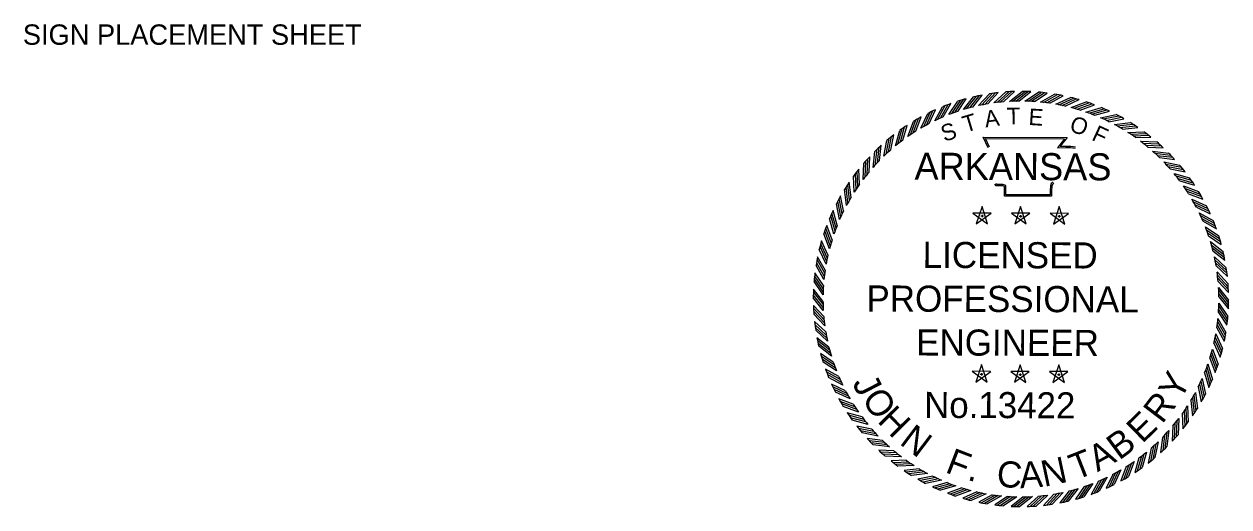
# Model space of a CAD drawing. Extents: x 620861 to 621178, y 415479 to 415559.
# Drawn here: x 621155.59 to 621178.3, y 415532.61 to 415541.71 of the extents above; entities that cross this region are included whole.
import ezdxf

# ---------------------------------------------------------------- set-up
doc = ezdxf.new("R2010")
doc.units = 0
doc.layers.add('Default', color=7, linetype='Continuous')
doc.layers.add('R_Border', color=7, linetype='Continuous')

# ---------------------------------------------------------------- blocks, each defined once
blk = doc.blocks.new('STAR')
at = {"layer": 'Default'}
for p, q in [((0.0587, 0.0188), (-0.059, 0.0189)), ((-0.0589, 0.0188), (0.0363, -0.0505)), ((-0.0001, 0.0615), (-0.0366, -0.0504)), ((-0.0365, -0.0503), (0.0589, 0.0188)), ((-0.0085, 0), (0.009, 0)), ((0.0362, -0.0503), (0, 0.0617)), ((0, 0.0063), (0, -0.0085))]:
    blk.add_line(p, q, dxfattribs=at)
blk = doc.blocks.new('RP')
at = {"layer": 'Default'}
for p, q in [((-0.0781, 1.2656), (0.003, 1.33)), ((-0.058, 1.2667), (0.0216, 1.3299)), ((-0.0375, 1.2674), (0.0405, 1.3294)), ((-0.0176, 1.2679), (0.059, 1.3287))]:
    blk.add_line(p, q, dxfattribs=at)
for radius, start, end in [(1.33, 87.45624, 89.86992), (1.268, 90.79335, 93.53072)]:
    blk.add_arc((0, 0), radius, start, end, dxfattribs=at)

msp = doc.modelspace()

# ---------------------------------------------------------------- linework, layer by layer
at = {"layer": 'Default'}
for points in [[(621173.763, 415539.378), (621173.672, 415539.577), (621175.255, 415539.572), (621175.122, 415539.407), (621175.23, 415539.408), (621175.32, 415539.409), (621175.409, 415539.399)], [(621173.786, 415539.389), (621173.711, 415539.552), (621175.203, 415539.548), (621175.07, 415539.381), (621175.23, 415539.383), (621175.318, 415539.384), (621175.407, 415539.374)], [(621175.003, 415538.711), (621174.976, 415538.689), (621174.967, 415538.656), (621174.957, 415538.574), (621174.957, 415538.465), (621174.073, 415538.468), (621174.074, 415538.615), (621174.074, 415538.648), (621174.038, 415538.659), (621173.912, 415538.66), (621173.89, 415538.694)], [(621174.987, 415538.73), (621174.954, 415538.703), (621174.942, 415538.661), (621174.932, 415538.576), (621174.932, 415538.49), (621174.098, 415538.493), (621174.099, 415538.615), (621174.099, 415538.667), (621174.042, 415538.684), (621173.926, 415538.685), (621173.911, 415538.708)]]:
    msp.add_lwpolyline(points, dxfattribs=at)

# ---------------------------------------------------------------- block references
for name, p, xscale, yscale, rotation in [('RP', (621174.382, 415536.528), 2.94327949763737, 2.9432794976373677, 13.30419999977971), ('RP', (621174.382, 415536.528), 2.9432794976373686, 2.9432794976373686, 8.804199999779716), ('RP', (621174.382, 415536.528), 2.9432794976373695, 2.9432794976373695, 4.304199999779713), ('RP', (621174.382, 415536.528), 2.9432794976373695, 2.943279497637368, -0.19580000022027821), ('RP', (621174.382, 415536.528), 2.9432794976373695, 2.943279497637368, -4.695800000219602), ('RP', (621174.382, 415536.528), 2.94327949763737, 2.9432794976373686, -9.195800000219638), ('RP', (621174.382, 415536.528), 2.94327949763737, 2.943279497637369, -13.695800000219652), ('RP', (621174.382, 415536.528), 2.9432794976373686, 2.9432794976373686, 22.304199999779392), ('RP', (621174.382, 415536.528), 2.943279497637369, 2.943279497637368, 17.80419999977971), ('RP', (621174.382, 415536.528), 2.94327949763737, 2.943279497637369, -18.19580000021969), ('RP', (621174.382, 415536.528), 2.9432794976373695, 2.943279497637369, -22.695800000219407), ('RP', (621174.382, 415536.528), 2.9432794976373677, 2.9432794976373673, 31.304199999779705), ('RP', (621174.382, 415536.528), 2.9432794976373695, 2.943279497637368, 26.8041999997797), ('RP', (621174.382, 415536.528), 2.943279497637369, 2.9432794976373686, -27.19580000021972), ('RP', (621174.382, 415536.528), 2.94327949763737, 2.9432794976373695, -31.69580000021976), ('RP', (621174.382, 415536.528), 2.9432794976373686, 2.943279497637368, 35.80419999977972), ('RP', (621174.382, 415536.528), 2.9432794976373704, 2.943279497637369, -36.19580000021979), ('RP', (621174.382, 415536.528), 2.9432794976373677, 2.943279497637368, 40.3041999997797), ('RP', (621174.382, 415536.528), 2.943279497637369, 2.9432794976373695, -40.69580000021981), ('RP', (621174.382, 415536.528), 2.943279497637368, 2.943279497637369, 44.804199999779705), ('RP', (621174.382, 415536.528), 2.943279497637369, 2.943279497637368, -45.19580000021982), ('RP', (621174.382, 415536.528), 2.943279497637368, 2.9432794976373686, -49.695800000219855), ('RP', (621174.382, 415536.528), 2.94327949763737, 2.9432794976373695, 49.30419999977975), ('RP', (621174.382, 415536.528), 2.9432794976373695, 2.943279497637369, 53.80419999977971), ('RP', (621174.382, 415536.528), 2.9432794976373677, 2.9432794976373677, -54.19580000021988), ('RP', (621174.382, 415536.528), 2.943279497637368, 2.9432794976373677, 58.30419999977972), ('RP', (621174.382, 415536.528), 2.9432794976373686, 2.9432794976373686, -58.69580000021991), ('RP', (621174.382, 415536.528), 2.9432794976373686, 2.943279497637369, 62.80419999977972), ('RP', (621174.382, 415536.528), 2.943279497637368, 2.9432794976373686, -63.19580000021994), ('RP', (621174.382, 415536.528), 2.9432794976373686, 2.943279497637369, 67.30419999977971), ('STAR', (621173.648, 415538.093), 2.9432794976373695, 2.943279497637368, -0.19580000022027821), ('STAR', (621174.376, 415538.091), 2.9432794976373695, 2.943279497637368, -0.19580000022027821), ('STAR', (621175.104, 415538.088), 2.9432794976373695, 2.943279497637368, -0.19580000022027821), ('RP', (621174.382, 415536.528), 2.943279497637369, 2.943279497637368, -67.69580000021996), ('RP', (621174.382, 415536.528), 2.943279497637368, 2.9432794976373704, 71.80419999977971), ('RP', (621174.382, 415536.528), 2.943279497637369, 2.9432794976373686, -72.19580000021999), ('RP', (621174.382, 415536.528), 2.9432794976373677, 2.9432794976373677, -76.69580000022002), ('RP', (621174.382, 415536.528), 2.9432794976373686, 2.943279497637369, 76.30419999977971), ('RP', (621174.382, 415536.528), 2.943279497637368, 2.943279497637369, 80.80419999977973), ('RP', (621174.382, 415536.528), 2.9432794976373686, 2.943279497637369, -81.19580000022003), ('RP', (621174.382, 415536.528), 2.9432794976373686, 2.9432794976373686, 85.30419999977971), ('RP', (621174.382, 415536.528), 2.943279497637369, 2.9432794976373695, -85.69580000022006), ('RP', (621174.382, 415536.528), 2.9432794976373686, 2.94327949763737, -90.19580000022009), ('RP', (621174.382, 415536.528), 2.9432794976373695, 2.9432794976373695, 89.80419999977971), ('RP', (621174.382, 415536.528), 2.943279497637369, 2.9432794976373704, 94.30419999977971), ('RP', (621174.382, 415536.528), 2.9432794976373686, 2.943279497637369, -94.69580000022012), ('RP', (621174.382, 415536.528), 2.943279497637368, 2.9432794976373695, 98.80419999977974), ('RP', (621174.382, 415536.528), 2.9432794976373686, 2.94327949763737, -99.19580000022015), ('RP', (621174.382, 415536.528), 2.9432794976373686, 2.94327949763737, 103.30419999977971), ('RP', (621174.382, 415536.528), 2.9432794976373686, 2.9432794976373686, -103.69580000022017), ('RP', (621174.382, 415536.528), 2.943279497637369, 2.94327949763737, 107.80419999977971), ('RP', (621174.382, 415536.528), 2.9432794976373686, 2.9432794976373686, -108.19580000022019), ('RP', (621174.382, 415536.528), 2.943279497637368, 2.9432794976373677, 112.30419999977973), ('STAR', (621173.638, 415535.108), 2.9432794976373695, 2.943279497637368, -0.19580000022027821), ('STAR', (621174.366, 415535.105), 2.9432794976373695, 2.943279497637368, -0.19580000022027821), ('STAR', (621175.094, 415535.103), 2.9432794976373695, 2.943279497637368, -0.19580000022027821), ('RP', (621174.382, 415536.528), 2.943279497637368, 2.9432794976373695, -112.69580000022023), ('RP', (621174.382, 415536.528), 2.943279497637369, 2.9432794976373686, 116.80419999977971), ('RP', (621174.382, 415536.528), 2.9432794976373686, 2.94327949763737, -117.19580000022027), ('RP', (621174.382, 415536.528), 2.943279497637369, 2.943279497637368, 121.30419999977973), ('RP', (621174.382, 415536.528), 2.9432794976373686, 2.94327949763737, -121.69580000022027), ('RP', (621174.382, 415536.528), 2.9432794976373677, 2.943279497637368, 125.80419999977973), ('RP', (621174.382, 415536.528), 2.9432794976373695, 2.94327949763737, -126.19580000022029), ('RP', (621174.382, 415536.528), 2.9432794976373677, 2.943279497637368, 130.30419999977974), ('RP', (621174.382, 415536.528), 2.943279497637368, 2.9432794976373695, -130.69580000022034), ('RP', (621174.382, 415536.528), 2.943279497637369, 2.943279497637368, 134.80419999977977), ('RP', (621174.382, 415536.528), 2.943279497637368, 2.943279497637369, -135.1958000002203), ('RP', (621174.382, 415536.528), 2.9432794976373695, 2.943279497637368, 139.3041999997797), ('RP', (621174.382, 415536.528), 2.9432794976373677, 2.943279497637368, -139.69580000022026), ('RP', (621174.382, 415536.528), 2.94327949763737, 2.9432794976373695, 143.80419999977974), ('RP', (621174.382, 415536.528), 2.9432794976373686, 2.943279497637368, -144.19580000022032), ('RP', (621174.382, 415536.528), 2.9432794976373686, 2.9432794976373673, 148.30419999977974), ('RP', (621174.382, 415536.528), 2.943279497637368, 2.9432794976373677, -148.69580000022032), ('RP', (621174.382, 415536.528), 2.9432794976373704, 2.943279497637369, 152.80419999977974), ('RP', (621174.382, 415536.528), 2.9432794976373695, 2.9432794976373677, 157.30419999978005), ('RP', (621174.382, 415536.528), 2.9432794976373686, 2.94327949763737, -157.69580000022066), ('RP', (621174.382, 415536.528), 2.9432794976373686, 2.943279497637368, -153.19580000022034), ('RP', (621174.382, 415536.528), 2.9432794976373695, 2.943279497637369, 161.8041999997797), ('RP', (621174.382, 415536.528), 2.9432794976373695, 2.943279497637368, 166.3041999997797), ('RP', (621174.382, 415536.528), 2.943279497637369, 2.9432794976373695, 170.80419999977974), ('RP', (621174.382, 415536.528), 2.9432794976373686, 2.9432794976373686, -171.1958000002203), ('RP', (621174.382, 415536.528), 2.943279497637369, 2.943279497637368, -166.69580000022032), ('RP', (621174.382, 415536.528), 2.943279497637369, 2.9432794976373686, -162.19580000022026), ('RP', (621174.382, 415536.528), 2.94327949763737, 2.9432794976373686, 175.30419999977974), ('RP', (621174.382, 415536.528), 2.9432794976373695, 2.943279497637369, 179.80419999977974), ('RP', (621174.382, 415536.528), 2.9432794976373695, 2.943279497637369, -175.69580000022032)]:
    msp.add_blockref(name, p, dxfattribs=dict(at, xscale=xscale, yscale=yscale, rotation=rotation))

# ---------------------------------------------------------------- texts
for s, height, rotation, p in [('T', 0.312, 16.7057, (621173.336, 415539.662)), ('A', 0.312, 8.483, (621173.716, 415539.76)), ('T', 0.312, 1.2831, (621174.119, 415539.821)), ('E', 0.312, 356.4762, (621174.519, 415539.81)), ('O', 0.312, 341.026, (621175.277, 415539.7)), ('S', 0.312, 19.5768, (621172.939, 415539.485)), ('F', 0.312, 335.167, (621175.697, 415539.534)), ('ARKANSAS', 0.5097, 359.8042, (621172.375, 415538.777)), ('LICENSED', 0.4934, 359.8042, (621172.528, 415537.113)), ('PROFESSIONAL', 0.49341, 359.8042, (621171.468, 415536.291)), ('ENGINEER', 0.4934, 359.8042, (621172.405, 415535.463)), ('Y', 0.493, 62.5392, (621177.39, 415534.591)), ('J', 0.493, 297.2813, (621171.193, 415534.942)), ('O', 0.493, 304.1899, (621171.367, 415534.639)), ('No.13422', 0.4915, 359.8042, (621172.556, 415534.286)), ('R', 0.493, 52.7437, (621177.045, 415534.157)), ('H', 0.493, 314.7447, (621171.658, 415534.214)), ('E', 0.493, 44.306, (621176.67, 415533.79)), ('N', 0.493, 322.9417, (621172.075, 415533.802)), ('B', 0.493, 36.505, (621176.234, 415533.476)), ('A', 0.493, 28.8562, (621175.824, 415533.26)), ('F', 0.493, 339.0288, (621172.936, 415533.267)), ('T', 0.493, 21.4329, (621175.414, 415533.106)), ('C', 0.493, 356.1028, (621173.915, 415532.99)), ('A', 0.493, 3.9092, (621174.368, 415532.958)), ('N', 0.493, 12.0703, (621174.819, 415532.983)), ('.', 0.493, 344.7037, (621173.357, 415533.121))]:
    msp.add_text(s, height=height, rotation=rotation, dxfattribs=at).set_placement(p)
at = {"layer": 'R_Border'}
msp.add_text('SIGN PLACEMENT SHEET', height=0.38386, rotation=0.0018, dxfattribs=at).set_placement((621155.566, 415541.321))

doc.saveas('drawing.dxf')
